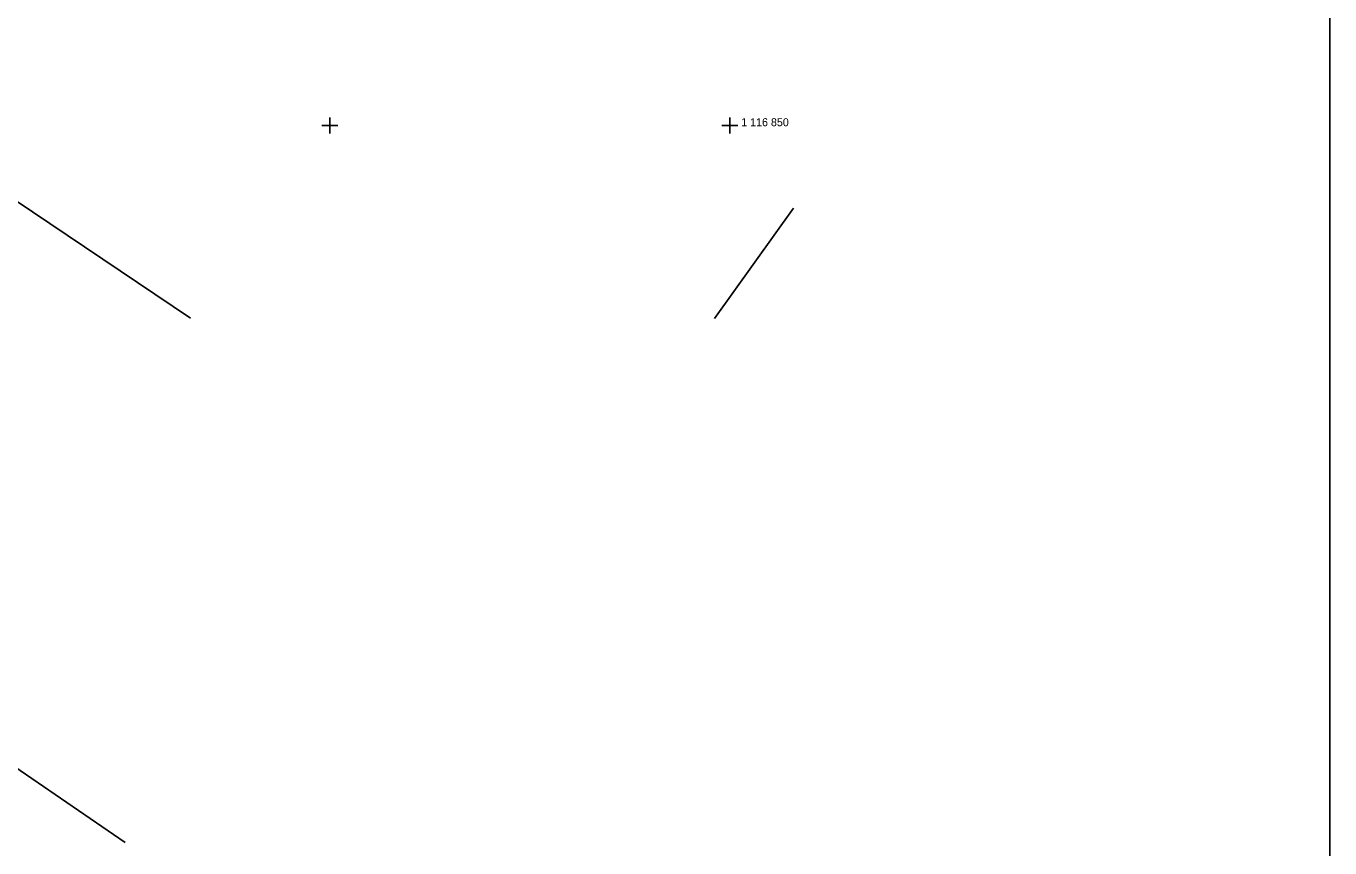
# Model space of a CAD drawing. Extents: x -504375 to -503125, y -1118000 to -1116474.
# Drawn here: x -503288 to -503125, y -1116940.3 to -1116837.6 of the extents above; entities that cross this region are included whole.
import ezdxf

# ---------------------------------------------------------------- set-up
doc = ezdxf.new("R2010")
doc.units = 0
for name, color, linetype in [('Podkladové mapy', 7, 'Continuous'), ('Síť dekadická', 7, 'Continuous'), ('Vrstva 34', 7, 'Continuous'), ('Vrstva 48', 7, 'Continuous')]:
    doc.layers.add(name, color=color, linetype=linetype)

msp = doc.modelspace()

# ---------------------------------------------------------------- linework, layer by layer
at = {"layer": 'Podkladové mapy'}
for p, q in [((-503267.418, -1116874.085), (-503297.87, -1116853.6)), ((-503192.069, -1116860.353), (-503201.906, -1116874.149)), ((-503275.591, -1116939.651), (-503340.94, -1116894.81))]:
    msp.add_line(p, q, dxfattribs=at)
at = {"layer": 'Síť dekadická'}
msp.add_lwpolyline([(-503125, -1116500), (-503125, -1117000), (-503750, -1117000), (-503750, -1116500)], close=True, dxfattribs=at)
at = {"layer": 'Vrstva 34'}
for p, q in [((-503249, -1116850), (-503251, -1116850)), ((-503250, -1116849), (-503250, -1116851)), ((-503199, -1116850), (-503201, -1116850)), ((-503200, -1116849), (-503200, -1116851))]:
    msp.add_line(p, q, dxfattribs=at)
at = {"layer": 'Vrstva 48'}
for points in [[(-503228.261, -1116563.145), (-503229.645, -1116567.016), (-503233.265, -1116571.228), (-503245.688, -1116584.541), (-503247.935, -1116586.867), (-503252.973, -1116594.854), (-503254.135, -1116607.338), (-503261.55, -1116616.428), (-503262.857, -1116617.898), (-503273.652, -1116628.941), (-503288.12, -1116641.769), (-503294.834, -1116647.413), (-503299.542, -1116653.756), (-503302.433, -1116657.068), (-503311.897, -1116663.915), (-503313.227, -1116667.667), (-503316.736, -1116674.505), (-503325.627, -1116690.3), (-503328.511, -1116695.009), (-503335.94, -1116707.278), (-503351.034, -1116723.382), (-503365.126, -1116737.245), (-503372.674, -1116748.782), (-503373.925, -1116753.16), (-503378.551, -1116760.666), (-503382.552, -1116767.547), (-503390.579, -1116780.739), (-503398.79, -1116793.818), (-503400.908, -1116797.881), (-503402.495, -1116807.226), (-503404.198, -1116812.046), (-503412.471, -1116822.312), (-503418.387, -1116829.995), (-503420.024, -1116835.788), (-503425.814, -1116843.155), (-503430.336, -1116857.921), (-503433.683, -1116863.223), (-503434.674, -1116865.019), (-503440.926, -1116880.75), (-503445.259, -1116893.88)], [(-503481.504, -1116663.518), (-503468.547, -1116657.036), (-503463.489, -1116655.349), (-503455.413, -1116652.508), (-503447.337, -1116652.508), (-503443.352, -1116653.982), (-503430.298, -1116650.555), (-503416.187, -1116635.106), (-503410.685, -1116628.713), (-503402.504, -1116619.064), (-503381.737, -1116613.158), (-503370.807, -1116610.971), (-503361.189, -1116605.649), (-503353.61, -1116601.494), (-503341.223, -1116596.974), (-503328.544, -1116591.798), (-503324.172, -1116589.392), (-503302.385, -1116583.924), (-503293.932, -1116583.924), (-503286.266, -1116582.08), (-503284.637, -1116580.965), (-503272.933, -1116568.697), (-503269.17, -1116566.723), (-503271.089, -1116569.984), (-503281.636, -1116583.324), (-503281.636, -1116584.01), (-503265.516, -1116590.53), (-503268.945, -1116595.892), (-503268.945, -1116601.682), (-503275.976, -1116612.148), (-503282.064, -1116615.751), (-503283.352, -1116619.8), (-503288.876, -1116631.779), (-503303.377, -1116644.015), (-503307.12, -1116648.093), (-503316.743, -1116659.793), (-503321.087, -1116663.538), (-503326.965, -1116676.097), (-503331.52, -1116684.914), (-503334.134, -1116690.218), (-503342.049, -1116704.413), (-503355.564, -1116718.999), (-503373.009, -1116735.836), (-503382.317, -1116749.959), (-503386.693, -1116758.655), (-503400.779, -1116777.303), (-503409.619, -1116795.183), (-503415, -1116808.93), (-503418.611, -1116811.169), (-503424.106, -1116823.61), (-503426.69, -1116826.983), (-503429.797, -1116836.064), (-503433.946, -1116846.027), (-503439.043, -1116851.839), (-503444.852, -1116860.972), (-503445.916, -1116865.085), (-503449.799, -1116874.02), (-503458.366, -1116891.656), (-503466.054, -1116907.093), (-503467.087, -1116909.659), (-503470.52, -1116921.657)]]:
    msp.add_spline(points, degree=3, dxfattribs=at)

# ---------------------------------------------------------------- texts
at = {"layer": 'Vrstva 34'}
msp.add_text('1 116 850', height=1, dxfattribs=at).set_placement((-503198.586, -1116850.102))

doc.saveas('drawing.dxf')
